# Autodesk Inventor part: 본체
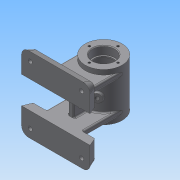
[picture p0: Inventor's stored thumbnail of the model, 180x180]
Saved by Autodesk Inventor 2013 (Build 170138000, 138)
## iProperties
Created: 2016-07
Part Number: 본체
Material: 일반
Document SubType Name: Modeling
Designer: Administrator
Density: 1 g/cm^3
Author: Administrator
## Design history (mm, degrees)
sketch "스케치1"
  geometry: C1 r 27 at (0, 0); 1 further point
  constraints: 1 centre point, 1 coincident
  dimensions: "d0" = 54 diameter of C1
extrude "돌출1" new body sketch "스케치1" distance "d1" = 35; taper "d2" = 0 deg
hole "구멍1" diameter "d5" = 28; stored, may be unused: countersink angle "d9" = 90 deg, drill point angle "d11" = 0 deg; dims "d3" = 10, "d4" = 10, "d6" = 6, "d7" = 32, "d8" = 12, "d10" = 14
sketch "스케치2"
  geometry: C1 r 27 at (0, 0) reference; C2 r 22 at (0, 0)
  constraints: 1 centre point, 1 coincident
  dimensions: "d12" = 44 diameter of C2
extrude "돌출2" cut sketch "스케치2" distance "d13" = 21; taper "d14" = 0 deg
chamfer "모따기1" distance "d15" = 1; stored, may be unused: second distance "d16" = 2, angle "d17" = 45 deg
fillet "모깎기1" dims "d18" = 0.3
sketch "스케치3"
  geometry: C1 r 27 at (0, 0) reference; 1 further point
  constraints: 1 vertical alignment
  dimensions: "d19" = 21 distance of C1.centre point (0, 21)
hole "구멍2" sketch "스케치3" at (0, 21) diameter "d20" = 3.242; stored, may be unused: countersink angle "d24" = 90 deg, drill point angle "d26" = 118 deg; dims "d21" = 8, "d22" = 32, "d23" = 12, "d25" = 10
node "작업 평면1"
node "작업 평면2"
sketch "스케치6"
  geometry: L1 (50, 20)-(-50, 20); L2 (-50, 20)-(-50, 45); L3 (-40, 55)-(40, 55); L4 (50, 45)-(50, 20); A1 r 10 centre (-40, 45) between (-40, 55) and (-50, 45); A2 r 10 centre (40, 45) between (50, 45) and (40, 55); 2 further points
  constraints: 8 end point, 4 point on circle, 4 tangent, 2 centre point, 2 parallel, 1 horizontal, 1 midpoint, 1 perpendicular, 1 vertical alignment
  dimensions: "d47" = 20 distance from line of L1 point (0, 0); "d50" = 20 diameter of A1; "d51" = 20 diameter of A2; "d52" = 35 distance between parallel lines of L3 L1; "d53" = 100 distance between parallel lines of L2 L4
node "작업 평면3"
sketch "스케치9"
  geometry: L1 (50, 20)-(-50, 20) reference; L2 (40, 50)-(-40, 50); L3 (-45, 20)-(45, 20); L4 (45, 45)-(45, 20); L5 (-45, 45)-(-45, 20); A1 r 5 centre (-40, 45) between (-40, 50) and (-45, 45); A2 r 5 centre (40, 45) between (45, 45) and (40, 50); 1 further point
  constraints: 8 end point, 4 point on circle, 2 centre point, 2 point on line, 2 tangent, 1 collinear, 1 perpendicular
  dimensions: "d74" = 5 radius of A2; "d76" = 5 radius of A1; "d78" = 30 distance between parallel lines of L1 L2; "d79" = 25 distance of L5.start L3.start
feature "로프트1" sketch "스케치9" dims "d80" = 0, "d81" = 90 deg, "d82" = 0, "d83" = 90 deg
sketch "스케치10"
  geometry: L1 (0, 0)-(90, 0) reference; L2 (18, 0)-(72, 0); L3 (72, 0)-(72, -8); L4 (72, -8)-(18, -8); L5 (18, -8)-(18, 0); 2 further points
  constraints: 8 end point, 2 midpoint, 2 parallel, 1 horizontal, 1 perpendicular
  dimensions: "d84" = 8 distance of L2.end L3.end; "d86" = 54 distance of L3.end L4.end
extrude "돌출7" join sketch "스케치10" stored distance "d87" = 12; taper "d88" = 0 deg
fillet "모깎기4" dims "d89" = 2
fillet "모깎기5" dims "d90" = 2
fillet "모깎기6" dims "d91" = 2
sketch "스케치11"
  geometry: L1 (16, 23.3)-(16, 34) reference; L2 (16, 34)-(17, 35) reference; L3 (17, 35)-(19.379, 35) reference; L4 (19.379, 35)-(19.379, 25) reference; L5 (19.379, 25)-(21, 24.026) reference; L6 (21, 24.026)-(22.621, 25) reference; L7 (22.621, 25)-(22.621, 35) reference; L8 (22.621, 35)-(27, 35) reference; L9 (27, 35)-(27, -35) reference; L10 (27, -35)-(22.621, -35) reference; L11 (22.621, -35)-(22.621, -25) reference; L12 (22.621, -25)-(21, -24.026) reference; L13 (21, -24.026)-(19.379, -25) reference; L14 (19.379, -25)-(19.379, -35) reference; L15 (19.379, -35)-(17, -35) reference; L16 (17, -35)-(16, -34) reference; L17 (16, -34)-(16, -23.3) reference; L18 (15.7, -23)-(14, -23) reference; L19 (14, -23)-(14, -21) reference; L20 (14, -21)-(22, -21) reference; L21 (22, -21)-(22, 21) reference; L22 (22, 21)-(14, 21) reference; L23 (14, 21)-(14, 23) reference; L24 (14, 23)-(15.7, 23) reference; L25 (-16, 34)-(-16, 23.3) reference; L26 (-15.7, 23)-(-14, 23) reference; L27 (-14, 23)-(-14, 21) reference; L28 (-14, 21)-(-22, 21) reference; L29 (-22, 21)-(-22, -21) reference; L30 (-22, -21)-(-14, -21) reference; L31 (-14, -21)-(-14, -23) reference; L32 (-14, -23)-(-15.7, -23) reference; L33 (-16, -23.3)-(-16, -34) reference; L34 (-16, -34)-(-17, -35) reference; L35 (-17, -35)-(-19.379, -35) reference; L36 (-19.379, -35)-(-19.379, -25) reference; L37 (-19.379, -25)-(-21, -24.026) reference; L38 (-21, -24.026)-(-22.621, -25) reference; L39 (-22.621, -25)-(-22.621, -35) reference; L40 (-22.621, -35)-(-27, -35) reference; L41 (-27, -35)-(-27, -28) reference; L42 (-27, -28)-(-56, -28) reference; L43 (-58, -30)-(-58, -48.667) reference; L44 (-59.231, -50.513)-(-70, -55) reference; L45 (-70, -55)-(-70, -20) reference; L46 (-70, -20)-(-27, -20) reference; L47 (-27, -20)-(-27, 20) reference; L48 (-27, 20)-(-70, 20) reference; L49 (-70, 20)-(-70, 55) reference; L50 (-70, 55)-(-59.231, 50.513) reference; L51 (-58, 48.667)-(-58, 30) reference; L52 (-56, 28)-(-27, 28) reference; L53 (-27, 28)-(-27, 35) reference; L54 (-27, 35)-(-22.621, 35) reference; L55 (-22.621, 35)-(-22.621, 25) reference; L56 (-22.621, 25)-(-21, 24.026) reference; L57 (-21, 24.026)-(-19.379, 25) reference; L58 (-19.379, 25)-(-19.379, 35) reference; L59 (-19.379, 35)-(-17, 35) reference; L60 (-17, 35)-(-16, 34) reference; L61 (-48, -13.682)-(-48, 17.027); A1 r 0.3 centre (15.7, -23.3) between (16, -23.3) and (15.7, -23) reference; A2 r 0.3 centre (15.7, 23.3) between (15.7, 23) and (16, 23.3) reference; A3 r 0.3 centre (-15.7, 23.3) between (-16, 23.3) and (-15.7, 23) reference; A4 r 0.3 centre (-15.7, -23.3) between (-15.7, -23) and (-16, -23.3) reference; A5 r 2 centre (-56, -30) between (-56, -28) and (-58, -30) reference; A6 r 2 centre (-60, -48.667) between (-59.231, -50.513) and (-58, -48.667) reference; A7 r 2 centre (-60, 48.667) between (-58, 48.667) and (-59.231, 50.513) reference; A8 r 2 centre (-56, 30) between (-58, 30) and (-56, 28) reference; 1 further point
  constraints: 2 end point, 1 perpendicular
  dimensions: "d92" = 21 distance between parallel lines of L47 L61
feature "리브1" sketch "스케치11" dims "d93" = 1, "d94" = 8, "d95" = 0, "d96" = 0, "d97" = 1, "d98" = 1
node "작업 평면4"
sketch "스케치12"
  geometry: L1 (-23, -55)-(-77, -55) reference; L2 (-28, -41)-(-28, 1) reference; C1 r 5 at (-50, -42); 1 further point
  constraints: 1 centre point, 1 vertical alignment
  dimensions: "d100" = 10 diameter of C1; "d102" = 22 distance of C1.centre point (-50, -20)
extrude "돌출8" join sketch "스케치12" stored distance "d103" = 12; taper "d104" = 0 deg
hole "구멍3" diameter "d107" = 5.188; stored, may be unused: countersink angle "d111" = 90 deg, drill point angle "d113" = 0 deg; dims "d105" = 10, "d106" = 10, "d108" = 8, "d109" = 32, "d110" = 12, "d112" = 15
sketch "스케치13"
  geometry: L1 (0, 0)-(15.898, -25.441); L2 (0, 0)-(0, -15.741)
  constraints: 4 end point, 1 vertical
  dimensions: "d114" = 30 distance of L1.start L1.end; "d115" = 32 deg angle of L1 L2
node "작업 평면5"
sketch "스케치14"
  geometry: C1 r 6 at (0, 0); 1 further point
  constraints: 1 centre point, 1 coincident
  dimensions: "d116" = 12 diameter of C1
extrude "돌출9" join sketch "스케치14" stored distance "d117" = 12; taper "d118" = 0 deg
sketch "스케치15"
  geometry: C1 r 6 at (0, 0) reference; 1 further point
  constraints: 1 coincident
hole "구멍4" sketch "스케치15" at (0, 0) diameter "d119" = 5.188; stored, may be unused: countersink angle "d123" = 90 deg, drill point angle "d125" = 0 deg; dims "d120" = 8, "d121" = 32, "d122" = 12, "d124" = 15
fillet "모깎기7" dims "d126" = 2
fillet "모깎기8" dims "d127" = 2
sketch "스케치16"
  geometry: C1 r 5 at (2.5, -6.167); 1 further point
  constraints: 1 centre point
  dimensions: "d128" = 42.5 vertical distance of point (40, -48.667) C1.centre; "d129" = 37.5 horizontal distance of point (40, -48.667) C1.centre; "d130" = 10 diameter of C1
extrude "돌출10" cut sketch "스케치16" distance "d131" = 4; taper "d132" = 0 deg
sketch "스케치17"
  geometry: C1 r 5 at (0, 0) reference; C2 r 3 at (0, 0); 1 further point
  constraints: 1 centre point, 1 coincident
  dimensions: "d133" = 6 diameter of C2
extrude "돌출11" cut sketch "스케치17" stored distance "d134" = 4; taper "d135" = 0 deg
sketch "스케치18"
  geometry: L1 (-28, 13.5)-(-12, 13.5); L2 (-28, 6.5)-(-12, 6.5); L3 (0, -22)-(25, -22) reference; A1 r 3.5 centre (-28, 10) between (-28, 13.5) and (-28, 6.5); A2 r 3.5 centre (-12, 10) between (-12, 6.5) and (-12, 13.5); 2 further points
  constraints: 4 end point, 4 point on circle, 4 tangent, 2 centre point, 1 equal radius, 1 horizontal alignment, 1 midpoint, 1 vertical alignment
  dimensions: "d136" = 7 diameter of A1; "d138" = 23 dimension on A2 A1; "d139" = 32 distance from line of L3 A2.centre
extrude "돌출12" cut sketch "스케치18" stored distance "d140" = 4; taper "d141" = 0 deg
fillet "모깎기9" dims "d142" = 2
fillet "모깎기10" dims "d143" = 2
fillet "모깎기11" dims "d144" = 2
node "작업 평면6"
sketch "스케치19"
  geometry: L1 (59.231, 50.513)-(70, 55) reference; L2 (70, 55)-(70, 20) reference; L3 (70, 20)-(57.621, 20) reference; L4 (56, 22)-(56, 26) reference; L5 (58, 29.464)-(58, 48.667) reference; L6 (56, 22)-(0, 22) reference; L7 (0, -22)-(0, 22) reference; L8 (0, -22)-(56, -22) reference; L9 (57.621, -20)-(70, -20) reference; L10 (70, -20)-(70, -55) reference; L11 (70, -55)-(59.231, -50.513) reference; L12 (58, -48.667)-(58, -29.464) reference; L13 (56, -26)-(56, -22) reference; L14 (56, 26)-(0, 26) reference; L15 (0, 22)-(0, 26) reference; L16 (0, -26)-(0, -22) reference; L17 (0, -26)-(56, -26) reference; L18 (0, 26)-(0, 35) reference; L19 (0, -35)-(0, -26) reference; L20 (27, -35)-(-27, -35) reference; L21 (-27, -35)-(-27, 35) reference; A1 r 2 centre (60, 48.667) between (59.231, 50.513) and (58, 48.667) reference; A2 r 2 centre (60, -48.667) between (58, -48.667) and (59.231, -50.513) reference; 2 further points
  constraints: 5 other
  dimensions: "d147" = 35 distance from line of point (0, 0) L20; "d149" = 27 distance from line of point (0, 0) L21
feature "엠보싱1" sketch "스케치19" dims "d150" = 1, "d151" = 0
node "솔리드1"
pattern_circular "원형 패턴1" dims angle "d28" = 360 deg
mirror "대칭1"
mirror "대칭2"
mirror "대칭3"
node "절단 모서리 투영1"
node "절단 모서리 투영2"
other parameters: "d62" = 12, "d145" = -27
